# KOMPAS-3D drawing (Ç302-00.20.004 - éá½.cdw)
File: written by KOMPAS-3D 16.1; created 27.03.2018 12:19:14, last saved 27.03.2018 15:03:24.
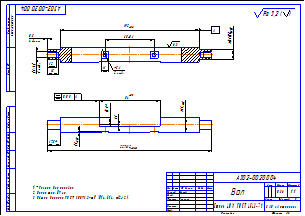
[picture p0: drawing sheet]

Sheet 1: A3, landscape

Title block, sheet 1: name: Вал; designation: А302-00.20.004; material: Сталь 40Х  ГОСТ 4543-71; mass: 0,36; scale: 1:1; sheets: 1; organisation: ЗАО «Астерион»; sheet format: A3; stored path: Z:\Мембранные насосы\Мембранный электропривод\А302-00.00.000 - ASTRA-302 (МЭ200)\Чертежи\А302-00.20.004 - Вал.cdw; drawn by: Милов; technical control: Лучихин

Views: Вид 1, Спереди, Проекционный вид 2, Местный разрез 1, Местный разрез 2
Referenced files in Z:\Мембранные насосы\Мембранный электропривод\А302-00.00.000 - ASTRA-302 (МЭ200)\3Д\: А302-00.20.004 - Вал.m3d
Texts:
  *Размер для справок.
  Покрытие: Ц9хр.
  Общие допуски ГОСТ 30893.2-mK (H14, h14,  t2/2).
  Ra 3,2
  Ra 3,2 ( )
Dimensions and other numbers on the sheet: 227; 17,5; 1,5; 84; 0,05; 20; 2,5; 12,5; 68±0,1; 5,1; 2 отв.; -6Н; 8; 0,5; 4 фаски; 12; 15; 192; 6,3; 13,5; 11; 1:1; 1; 0,36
